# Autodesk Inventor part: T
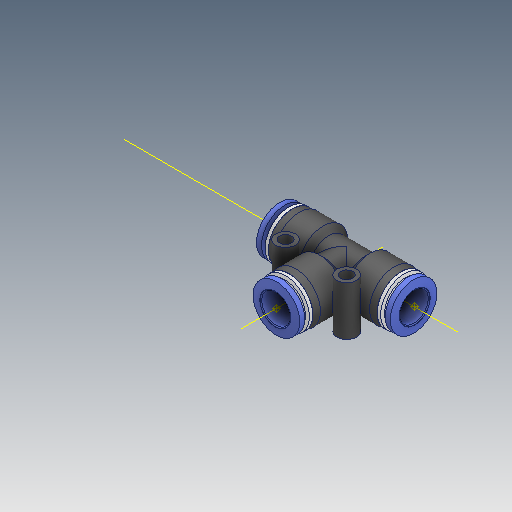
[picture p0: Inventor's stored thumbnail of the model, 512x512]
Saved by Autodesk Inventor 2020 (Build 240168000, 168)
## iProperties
Created: 2021-05
Part Number: T
Material: Polypropylen
Description: STEP AP214
Document SubType Name: Modeling
Designer: doma
Density: 0.899 g/cm^3
Appearance: Hladká – popel
Mass: 8.18174 g
Surface Area: 76.5367 cm^2
Volume: 9.10093 cm^3
Sending System: SolidWorks 2017
Preprocessor: SwSTEP 2.0
Title: UNIÃO T.STEP
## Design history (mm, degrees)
feature "Ø10 UNIÃO T (C00601000)_4:1"
node "Pracovní bod1"
node "Pracovní bod2"
node "Pracovní bod3"
node "Pracovní bod4"
  node "Pracovní osa3"
  node "Pracovní osa4"
node "Těleso1"
node "Těleso4"
